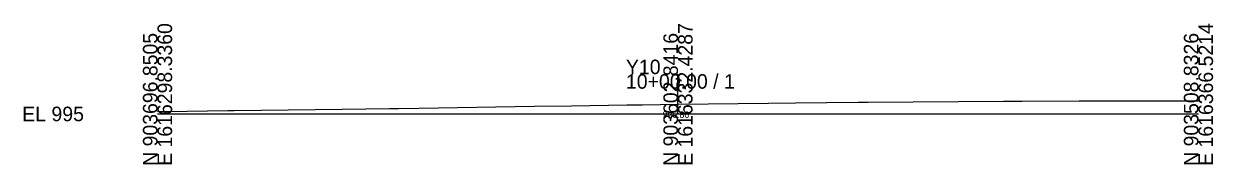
# Model space of a CAD drawing. Extents: x -26 to 203, y -10 to 3046.
# Drawn here: x -25.7 to 202.8, y -9.7 to 17.4 of the extents above; entities that cross this region are included whole.
import ezdxf

# ---------------------------------------------------------------- set-up
doc = ezdxf.new("R2010")
doc.units = 0
for name, color, linetype in [('Exist Cross Section Cell', 7, 'Continuous'), ('Exist XS Center Line Elevation Label', 7, 'Continuous'), ('Exist XS Ground Line', 7, 'Continuous')]:
    doc.layers.add(name, color=color, linetype=linetype)

msp = doc.modelspace()

# ---------------------------------------------------------------- linework, layer by layer
at = {"layer": 'Exist Cross Section Cell'}
for p, q in [((100, 0), (100, 7.66)), ((0, 0), (100, 0)), ((100, 0), (200, 0))]:
    msp.add_line(p, q, dxfattribs=at)
at = {"layer": 'Exist XS Ground Line'}
for p, q in [((136.55, 2.26), (162.53, 2.43)), ((162.53, 2.43), (166.16, 2.46)), ((166.16, 2.46), (177.07, 2.53)), ((177.07, 2.53), (178.62, 2.53)), ((178.62, 2.53), (200, 2.55)), ((0, 0.5), (5.73, 0.56)), ((5.73, 0.56), (13.51, 0.65)), ((13.51, 0.65), (14.71, 0.66)), ((14.71, 0.66), (35.47, 0.92)), ((35.47, 0.92), (44.55, 1.03)), ((44.55, 1.03), (46.31, 1.05)), ((46.31, 1.05), (50.19, 1.12)), ((50.19, 1.12), (72.42, 1.47)), ((72.42, 1.47), (79.53, 1.58)), ((79.53, 1.58), (90.19, 1.75)), ((90.19, 1.75), (93.18, 1.78)), ((93.18, 1.78), (100, 1.86)), ((100, 1.86), (117.41, 2.05)), ((117.41, 2.05), (122.59, 2.11)), ((122.59, 2.11), (134.65, 2.24)), ((134.65, 2.24), (136.55, 2.26))]:
    msp.add_line(p, q, dxfattribs=at)

# ---------------------------------------------------------------- texts
at = {"layer": 'Exist Cross Section Cell'}
for s, p in [('E 1616298.3360', (2.8, -10)), ('E 1616332.4287', (102.8, -10)), ('E 1616366.5214', (202.8, -10)), ('N 903696.8505', (0, -10)), ('N 903602.8416', (100, -10)), ('N 903508.8326', (200, -10))]:
    msp.add_text(s, height=2.8, rotation=90, dxfattribs=at).set_placement(p)
for s, p in [('Y10', (90, 7.66)), ('10+00.00 / 1', (90, 4.86)), ('EL 995', (-26, -1.4))]:
    msp.add_text(s, height=2.8, dxfattribs=at).set_placement(p)
at = {"layer": 'Exist XS Center Line Elevation Label'}
msp.add_text('996.86', height=1.25, dxfattribs=at).set_placement((97.04, -0.77))

doc.saveas('drawing.dxf')
